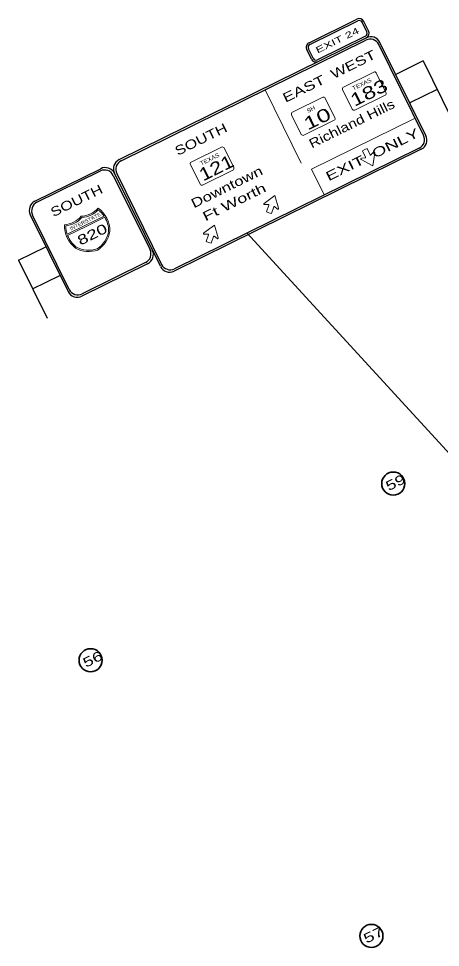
# Model space of a CAD drawing. Extents: x 2356431 to 2371438, y 6972864 to 6982525.
# Drawn here: x 2368252 to 2368867, y 6980796 to 6982152 of the extents above; entities that cross this region are included whole.
import ezdxf
from ezdxf.enums import TextEntityAlignment as Align

# ---------------------------------------------------------------- set-up
doc = ezdxf.new("R2010")
doc.units = 0
doc.header["$LTSCALE"] = 5.6
for name, color, linetype, lineweight in [('1', 7, 'Continuous', 25), ('17', 7, 'Continuous', 35), ('53', 7, 'Continuous', 13)]:
    doc.layers.add(name, color=color, linetype=linetype, lineweight=lineweight)

msp = doc.modelspace()

# ---------------------------------------------------------------- linework, layer by layer
at = {"layer": '1'}
for p, q in [((2368675.319, 6982116.666), (2368745.279, 6982151.181)), ((2368676.561, 6982114.147), (2368746.519, 6982148.66)), ((2368759.631, 6982132.668), (2368752.795, 6982146.527)), ((2368762.158, 6982133.913), (2368755.319, 6982147.773)), ((2368398.251, 6981946.036), (2368758.748, 6982123.867)), ((2368401.177, 6981944.344), (2368758.298, 6982120.542)), ((2368757.503, 6982126.387), (2368687.544, 6982091.884)), ((2368845.846, 6981981.209), (2368778.826, 6982117.058)), ((2368678.74, 6982092.767), (2368671.911, 6982106.626)), ((2368681.265, 6982094.014), (2368674.434, 6982107.869)), ((2368842.497, 6981981.651), (2368777.14, 6982114.138)), ((2368841.643, 6982090.178), (2368801.879, 6982070.495)), ((2368841.643, 6982090.178), (2368883.358, 6982005.903)), ((2368862.226, 6982048.594), (2368822.461, 6982028.913)), ((2368839.02, 6981961.139), (2368478.534, 6981783.285)), ((2368836.09, 6981962.826), (2368478.971, 6981786.635)), ((2368275.453, 6981885.455), (2368371.344, 6981932.758)), ((2368278.374, 6981883.767), (2368370.903, 6981929.41)), ((2368389.738, 6981923.023), (2368443.275, 6981814.492)), ((2368391.436, 6981925.95), (2368458.066, 6981790.871)), ((2368394.791, 6981925.513), (2368460.139, 6981793.025)), ((2368268.644, 6981865.366), (2368323.836, 6981753.469)), ((2368325.528, 6981756.396), (2368271.981, 6981864.937)), ((2368251.527, 6981799.091), (2368291.346, 6981818.663)), ((2368251.527, 6981799.091), (2368293.012, 6981714.703)), ((2368439.803, 6981793.964), (2368343.92, 6981746.665)), ((2368436.888, 6981795.655), (2368344.361, 6981750.013)), ((2368271.997, 6981757.453), (2368311.815, 6981777.026))]:
    msp.add_line(p, q, dxfattribs=at)
at = {"layer": '1', "lineweight": 13}
for p, q in [((2368769.695, 6982073.82), (2368725.543, 6982052.043)), ((2368787.586, 6982043.91), (2368773.462, 6982072.545)), ((2368611.187, 6982047.96), (2368664.067, 6981940.752)), ((2368695.289, 6982037.11), (2368651.137, 6982015.323)), ((2368713.196, 6982007.195), (2368699.062, 6982035.84)), ((2368724.26, 6982048.276), (2368738.39, 6982019.646)), ((2368742.157, 6982018.361), (2368786.303, 6982040.143)), ((2368649.854, 6982011.565), (2368663.984, 6981982.925)), ((2368667.755, 6981981.645), (2368711.908, 6982003.433)), ((2368830.209, 6982006.562), (2368679.023, 6981931.972)), ((2368547.631, 6981964.274), (2368503.463, 6981942.493)), ((2368565.514, 6981934.351), (2368551.392, 6981962.995)), ((2368502.19, 6981938.725), (2368516.312, 6981910.08)), ((2368520.082, 6981908.806), (2368564.243, 6981930.583)), ((2368679.023, 6981931.971), (2368697.523, 6981894.461)), ((2368376.187, 6981863.564), (2368349.284, 6981850.281)), ((2368377.2, 6981861.955), (2368350.116, 6981848.592)), ((2368322.377, 6981837.025), (2368349.284, 6981850.281)), ((2368323.05, 6981835.232), (2368350.116, 6981848.592)), ((2369000.307, 6981385.132), (2368584.339, 6981838.897))]:
    msp.add_line(p, q, dxfattribs=at)
at = {"layer": '1'}
for centre, radius, start, end in [((2368748.594, 6982144.453), 7.501, 26.25603, 116.25603), ((2368748.594, 6982144.453), 4.688, 26.25603, 116.25603), ((2368755.43, 6982130.595), 4.688, 296.25603, 26.25603), ((2368755.43, 6982130.595), 7.501, 296.25603, 26.25603), ((2368678.635, 6982109.944), 7.501, 116.25603, 206.25603), ((2368764.528, 6982107.911), 14.063, 26.25648, 116.25648), ((2368765.38, 6982110.422), 15.001, 26.25647, 116.25647), ((2368678.635, 6982109.944), 4.688, 116.25603, 206.25603), ((2368685.471, 6982096.086), 7.501, 206.25603, 296.25603), ((2368685.471, 6982096.086), 4.688, 206.25603, 296.25603), ((2368829.881, 6981975.428), 14.063, 296.25648, 26.25648), ((2368832.392, 6981974.576), 15.001, 296.25648, 26.25648), ((2368404.886, 6981932.584), 15.001, 116.25589, 206.25589), ((2368407.398, 6981931.732), 14.063, 116.25589, 206.25589), ((2368377.129, 6981916.801), 14.063, 26.25826, 116.25826), ((2368377.981, 6981919.312), 15.001, 26.25826, 116.25826), ((2368282.087, 6981872.006), 15.001, 116.25826, 206.25826), ((2368284.598, 6981871.154), 14.063, 116.25826, 206.25826), ((2368430.669, 6981808.271), 14.063, 296.25826, 26.25826), ((2368433.18, 6981807.419), 15.001, 296.25826, 26.25826), ((2368472.75, 6981799.249), 14.063, 206.25589, 296.25589), ((2368471.898, 6981796.738), 15.001, 206.25589, 296.25589), ((2368337.286, 6981760.113), 15.001, 206.25826, 296.25826), ((2368338.138, 6981762.624), 14.063, 206.25826, 296.25826)]:
    msp.add_arc(centre, radius, start, end, dxfattribs=at)
at = {"layer": '1', "lineweight": 13}
for centre, radius, start, end in [((2368770.94, 6982071.307), 2.813, 26.25538, 116.25538), ((2368726.78, 6982049.524), 2.813, 116.25537, 206.25537), ((2368696.54, 6982034.59), 2.813, 26.25648, 116.25648), ((2368785.066, 6982042.668), 2.813, 296.25538, 26.25538), ((2368652.38, 6982012.807), 2.813, 116.25647, 206.25647), ((2368740.906, 6982020.886), 2.813, 206.25537, 296.25537), ((2368710.666, 6982005.952), 2.813, 296.25648, 26.25648), ((2368666.507, 6981984.169), 2.813, 206.25648, 296.25648), ((2368548.871, 6981961.75), 2.813, 26.25588, 116.25588), ((2368504.712, 6981939.967), 2.813, 116.25588, 206.25588), ((2368562.998, 6981933.112), 2.813, 296.25588, 26.25588), ((2368518.838, 6981911.329), 2.813, 206.25588, 296.25588), ((2368340.711, 6981899.219), 35.984, 273.43865, 318.28896), ((2368340.711, 6981899.219), 37.874, 274.63656, 315.6334), ((2368342.809, 6981841.411), 41.954, 0.12145, 53.82382), ((2368342.809, 6981841.411), 40.064, 33.56789, 51.43264), ((2368315.679, 6981886.871), 35.984, 274.22756, 319.07787), ((2368315.679, 6981886.871), 37.874, 276.88312, 317.87996), ((2368342.809, 6981841.411), 40.064, 0.33798, 30.84997), ((2368360.275, 6981850.028), 41.954, 178.6927, 232.39508), ((2368360.275, 6981850.028), 40.064, 181.08388, 198.94863), ((2368360.275, 6981850.028), 40.064, 201.66656, 232.17854), ((2368344.57, 6981847.89), 38.808, 304.0963, 350.74268), ((2368344.57, 6981847.89), 40.698, 303.73016, 350.96606), ((2368354.062, 6981852.573), 38.808, 241.77384, 288.42022), ((2368354.062, 6981852.573), 40.698, 241.55046, 288.78636)]:
    msp.add_arc(centre, radius, start, end, dxfattribs=at)
at = {"layer": '17'}
for centre in [(2368798.219, 6981473.045), (2368356.526, 6981215.127), (2368766.355, 6980812.588)]:
    msp.add_circle(centre, 16.828, dxfattribs=at)
at = {"layer": '53'}
for p, q in [((2368769.422, 6981956.798), (2368765.602, 6981952.809)), ((2368751.331, 6981946.144), (2368751.349, 6981946.13)), ((2368757.192, 6981948.649), (2368751.681, 6981948.045)), ((2368609.852, 6981882.111), (2368625.331, 6981893.41)), ((2368625.331, 6981893.41), (2368630.745, 6981875.017)), ((2368615.944, 6981880.373), (2368610.422, 6981880.254)), ((2368629.155, 6981873.898), (2368624.832, 6981877.369)), ((2368521.775, 6981838.888), (2368537.253, 6981850.186)), ((2368537.253, 6981850.186), (2368542.666, 6981831.794)), ((2368527.866, 6981837.149), (2368522.345, 6981837.031)), ((2368541.078, 6981830.674), (2368536.754, 6981834.145))]:
    msp.add_line(p, q, dxfattribs=at)
for points in [[(2368751.349, 6981946.13), (2368768.182, 6981936.952), (2368771.138, 6981955.886)], [(2368764.495, 6981952.968), (2368759.903, 6981962.278), (2368756.503, 6981960.593), (2368753.118, 6981958.932), (2368757.721, 6981949.622)], [(2368623.769, 6981877.054), (2368620.441, 6981867.216), (2368616.874, 6981868.435), (2368613.276, 6981869.645), (2368616.613, 6981879.48)], [(2368535.69, 6981833.83), (2368532.361, 6981823.992), (2368528.794, 6981825.211), (2368525.198, 6981826.423), (2368528.536, 6981836.254)]]:
    msp.add_lwpolyline(points, dxfattribs=at)
for centre, radius, start, end in [((2368770.152, 6981956.081), 1.012, 350.99497, 136.37611), ((2368751.813, 6981947.034), 1.012, 96.13684, 241.51798), ((2368757.124, 6981949.309), 0.675, 276.27337, 26.25647), ((2368765.115, 6981953.251), 0.675, 206.25648, 316.23958), ((2368610.413, 6981881.277), 1.012, 125.99497, 271.37611), ((2368615.975, 6981879.717), 0.675, 341.25648, 91.23958), ((2368624.413, 6981876.853), 0.675, 51.27337, 161.25647), ((2368629.777, 6981874.707), 1.012, 231.13684, 16.51798), ((2368522.335, 6981838.054), 1.012, 125.99497, 271.37611), ((2368527.897, 6981836.493), 0.675, 341.25648, 91.23958), ((2368536.335, 6981833.629), 0.675, 51.27337, 161.25647), ((2368541.699, 6981831.483), 1.012, 231.13684, 16.51798)]:
    msp.add_arc(centre, radius, start, end, dxfattribs=at)

# ---------------------------------------------------------------- texts
at = {"layer": '1'}
for s, height, rotation, width, p in [('EXIT 24', 9.188, 26.256, 1.55, (2368718.672, 6982116.107)), ('WEST', 13.5, 26.255, 1.35, (2368742.665, 6982079.123)), ('EAST', 13.5, 26.255, 1.4, (2368670.617, 6982043.585)), ('Richland Hills', 13.5, 26.256, 1.25, (2368740.649, 6981992.37)), ('SOUTH', 13.5, 26.256, 1.3, (2368520.597, 6981969.569)), ('EXIT  ONLY', 13.5, 26.256, 1.5, (2368770.579, 6981947.277)), ('Downtown', 13.5, 26.256, 1.35, (2368558.33, 6981900.003)), ('SOUTH', 13.5, 26.258, 1.3, (2368339.048, 6981880.023)), ('Ft Worth', 13.5, 26.256, 1.45, (2368569.166, 6981878.032))]:
    msp.add_text(s, height=height, rotation=rotation, dxfattribs=dict(at, width=width)).set_placement(p, align=Align.CENTER)
for s, height, rotation, width, p in [('183', 18.75, 26.255, 1.35, (2368741.506, 6982022.959)), ('TEXAS', 6, 26.255, 1.15, (2368740.173, 6982046.883)), ('SH', 6, 26.256, 1.15, (2368673.668, 6982014.069)), ('10', 18.75, 26.256, 1.45, (2368673.374, 6981988.395)), ('TEXAS', 6, 26.256, 1.15, (2368518.1, 6981937.327)), ('121', 18.75, 26.256, 1.25, (2368520.705, 6981914.028)), ('INTERSTATE', 5.197, 26.258, 1.15, (2368327.816, 6981842.399)), ('820', 14.18, 26.258, 1.45, (2368341.594, 6981820.363))]:
    msp.add_text(s, height=height, rotation=rotation, dxfattribs=dict(at, width=width)).set_placement(p)
at = {"layer": '17'}
for s, width, p in [('59', 1.4, (2368804.514, 6981468.346)), ('56', 1.4, (2368362.821, 6981210.427)), ('57', 1.45, (2368772.601, 6980807.864))]:
    msp.add_text(s, height=14, rotation=26.268, dxfattribs=dict(at, width=width)).set_placement(p, align=Align.CENTER)

doc.saveas('drawing.dxf')
